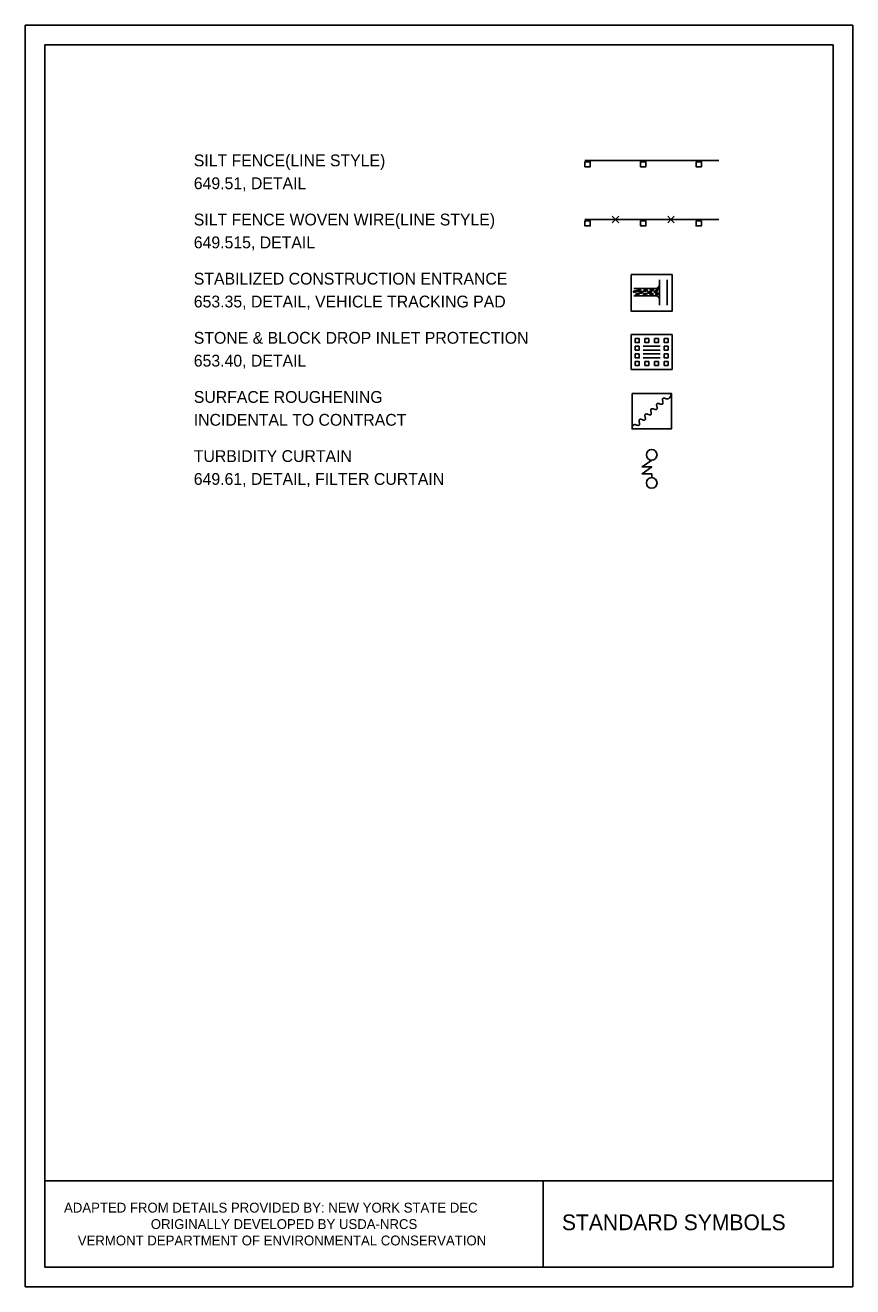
# Model space of a CAD drawing. Extents: x 0 to 556, y -320 to 0.
# Drawn here: x 346.4 to 556.4, y -320 to 0 of the extents above; entities that cross this region are included whole.
import ezdxf

# ---------------------------------------------------------------- set-up
doc = ezdxf.new("R2010")
doc.units = 0
for name, color, linetype in [('Level 6', 7, 'Continuous'), ('NBC1', 7, 'Continuous'), ('NBL1', 7, 'Continuous'), ('NBL1_T', 7, 'Continuous'), ('ODIM_T', 7, 'Continuous')]:
    doc.layers.add(name, color=color, linetype=linetype)

msp = doc.modelspace()

# ---------------------------------------------------------------- linework, layer by layer
at = {"layer": 'Level 6'}
for p, q in [((488.37, -34.29), (522.37, -34.29)), ((488.37, -49.29), (522.37, -49.29)), ((496.16, -49.29), (495.32, -48.45)), ((495.32, -50.14), (496.16, -49.29)), ((496.16, -49.29), (497.01, -48.45)), ((496.16, -49.29), (497.01, -50.14)), ((510.26, -49.29), (509.42, -48.45)), ((509.42, -50.14), (510.26, -49.29)), ((510.26, -49.29), (511.1, -48.45)), ((510.26, -49.29), (511.1, -50.14)), ((500.85, -66.75), (506.41, -66.75)), ((507.36, -64.61), (507.36, -71.02)), ((509.27, -64.61), (509.27, -71.02)), ((500.85, -68.65), (506.41, -68.65)), ((503.19, -81.42), (507.54, -81.42)), ((507.54, -82.42), (503.19, -82.42)), ((503.19, -83.37), (507.54, -83.37)), ((507.54, -84.37), (503.19, -84.37))]:
    msp.add_line(p, q, dxfattribs=at)
for points in [[(488.44, -34.63), (489.79, -34.63), (489.79, -35.89), (488.44, -35.89)], [(502.54, -34.63), (503.89, -34.63), (503.89, -35.89), (502.54, -35.89)], [(516.64, -34.63), (517.98, -34.63), (517.98, -35.89), (516.64, -35.89)], [(488.44, -49.63), (489.79, -49.63), (489.79, -50.89), (488.44, -50.89)], [(502.54, -49.63), (503.89, -49.63), (503.89, -50.89), (502.54, -50.89)], [(516.64, -49.63), (517.98, -49.63), (517.98, -50.89), (516.64, -50.89)], [(500.19, -63.23), (510.54, -63.23), (510.54, -72.56), (500.19, -72.56)], [(500.19, -78.48), (510.54, -78.48), (510.54, -87.31), (500.19, -87.31)], [(501.19, -79.48), (502.19, -79.48), (502.19, -80.48), (501.19, -80.48)], [(503.64, -79.48), (504.64, -79.48), (504.64, -80.48), (503.64, -80.48)], [(506.09, -79.48), (507.09, -79.48), (507.09, -80.48), (506.09, -80.48)], [(508.54, -79.48), (509.54, -79.48), (509.54, -80.48), (508.54, -80.48)], [(502.19, -81.42), (501.19, -81.42), (501.19, -82.42), (502.19, -82.42)], [(508.54, -81.42), (509.54, -81.42), (509.54, -82.42), (508.54, -82.42)], [(502.19, -83.37), (501.19, -83.37), (501.19, -84.37), (502.19, -84.37)], [(501.19, -86.31), (502.19, -86.31), (502.19, -85.31), (501.19, -85.31)], [(503.64, -86.31), (504.64, -86.31), (504.64, -85.31), (503.64, -85.31)], [(506.09, -86.31), (507.09, -86.31), (507.09, -85.31), (506.09, -85.31)], [(508.54, -83.37), (509.54, -83.37), (509.54, -84.37), (508.54, -84.37)], [(508.54, -86.31), (509.54, -86.31), (509.54, -85.31), (508.54, -85.31)], [(500.37, -93.39), (510.37, -93.39), (510.37, -102.39), (500.37, -102.39)]]:
    msp.add_lwpolyline(points, close=True, dxfattribs=at)
msp.add_lwpolyline([(505.37, -110.31), (502.91, -112.03), (505.37, -112.03), (502.91, -113.76), (505.37, -113.76), (505.37, -114.76)], dxfattribs=at)
for centre in [(505.37, -108.96), (505.37, -116.11)]:
    msp.add_circle(centre, 1.35, dxfattribs=at)
for centre, start, end in [((506.41, -65.8), 270, 360), ((506.41, -69.6), 360, 90)]:
    msp.add_arc(centre, 0.951, start, end, dxfattribs=at)
for centre in [(502.14, -67.23), (503.83, -67.23), (505.42, -67.13), (506.85, -66.92), (501.12, -67.54), (501.73, -68.25), (502.75, -67.74), (503.68, -68.25), (504.8, -67.74), (505.32, -68.25), (506.34, -67.54), (506.75, -68.15)]:
    msp.add_ellipse(centre, major_axis=(-0.461, -0.102), ratio=0.447214, dxfattribs=at)
msp.add_open_spline([(500.37, -102.39), (500.44, -100.98), (502.52, -101.8), (501.93, -99.64), (504.01, -100.46), (503.41, -98.31), (505.5, -99.12), (504.9, -96.97), (506.98, -97.79), (506.39, -95.63), (508.47, -96.45), (507.87, -94.29), (509.96, -95.11), (510.37, -93.39)], degree=2, dxfattribs=at)
at = {"layer": 'NBC1'}
msp.add_lwpolyline([(346.39, 0), (556.39, 0), (556.39, -320), (346.39, -320)], close=True, dxfattribs=at)
at = {"layer": 'NBL1'}
msp.add_line((477.79, -293.13), (477.79, -315), dxfattribs=at)
msp.add_lwpolyline([(351.39, -5), (551.39, -5), (551.39, -315), (351.39, -315)], close=True, dxfattribs=at)
msp.add_lwpolyline([(551.39, -293.13), (351.39, -293.13)], dxfattribs=at)

# ---------------------------------------------------------------- texts
at = {"layer": 'NBL1_T'}
for s, height, p in [('ADAPTED FROM DETAILS PROVIDED BY: NEW YORK STATE DEC', 2.5, (356.24, -301.18)), ('ORIGINALLY DEVELOPED BY USDA-NRCS', 2.5, (378.26, -305.35)), ('STANDARD SYMBOLS', 4, (482.59, -305.65)), ('VERMONT DEPARTMENT OF ENVIRONMENTAL CONSERVATION', 2.5, (359.73, -309.51))]:
    msp.add_text(s, height=height, dxfattribs=at).set_placement(p)
at = {"layer": 'ODIM_T'}
for s, p in [('SILT FENCE(LINE STYLE)', (389.17, -35.79)), ('649.51, DETAIL', (389.17, -41.59)), ('SILT FENCE WOVEN WIRE(LINE STYLE)', (389.17, -50.79)), ('649.515, DETAIL', (389.17, -56.59)), ('STABILIZED CONSTRUCTION ENTRANCE', (389.17, -65.79)), ('653.35, DETAIL, VEHICLE TRACKING PAD', (389.17, -71.59)), ('STONE & BLOCK DROP INLET PROTECTION', (389.17, -80.79)), ('653.40, DETAIL', (389.17, -86.59)), ('SURFACE ROUGHENING', (389.17, -95.79)), ('INCIDENTAL TO CONTRACT', (389.17, -101.59)), ('TURBIDITY CURTAIN', (389.17, -110.79)), ('649.61, DETAIL, FILTER CURTAIN', (389.17, -116.59))]:
    msp.add_text(s, height=3, dxfattribs=at).set_placement(p)

doc.saveas('drawing.dxf')
